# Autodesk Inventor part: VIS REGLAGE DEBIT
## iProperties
Created: 2004-11
Part Number: VIS REGLAGE DEBIT
Document SubType Name: Modeling
Designer: Bruno
Manufacturer: Standard
Standards Organization: Custom
Author: Bruno
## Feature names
1. Base1
2. Chanfrein1 [Chamfer]
